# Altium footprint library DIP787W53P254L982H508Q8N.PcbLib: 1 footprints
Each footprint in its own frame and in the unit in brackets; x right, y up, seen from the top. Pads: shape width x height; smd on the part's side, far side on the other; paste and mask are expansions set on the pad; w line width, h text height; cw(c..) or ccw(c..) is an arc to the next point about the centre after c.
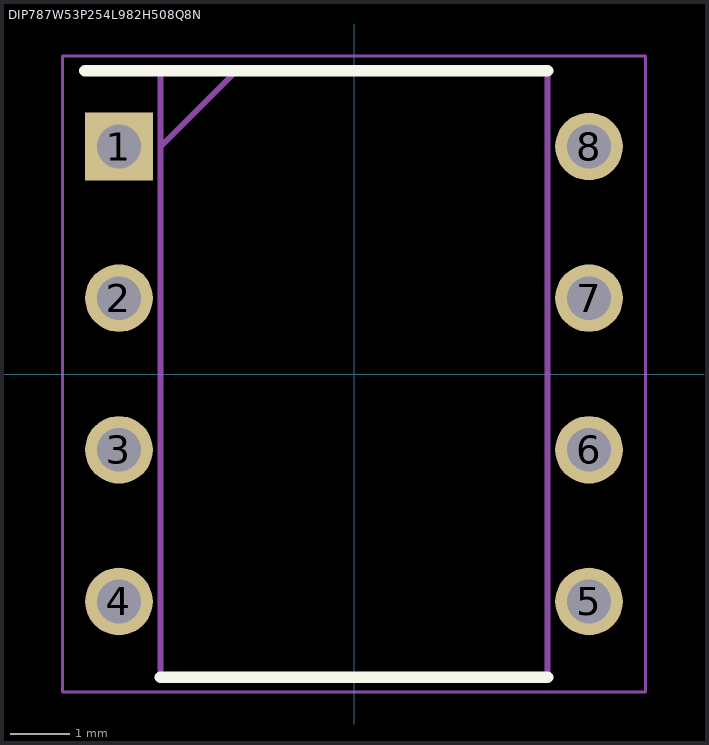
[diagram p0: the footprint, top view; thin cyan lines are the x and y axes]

## DIP787W53P254L982H508Q8N [mil]
pads (8):
  rect 44.61x44.61 / inner round 44.61 / far side rect 44.61x44.61 hole 28.86: 1(-155,150)
  round 44.61 hole 28.86: 2(-155,50) 3(-155,-50) 4(-155,-150) 5(155,-150) 6(155,-50) 7(155,50) 8(155,150)
Top Overlay:
  lines w7.87: -177.32,200 127.48,200 ; -127.48,-200 127.48,-200
Mechanical 15:
  lines w3.94: -127.48,150 -77.48,200 ; -127.48,-200 127.48,-200 127.48,200 -127.48,200 -127.48,-200
Mechanical 20:
  lines w1.97: -192.13,-209.84 192.13,-209.84 192.13,209.84 -192.13,209.84 -192.13,-209.84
